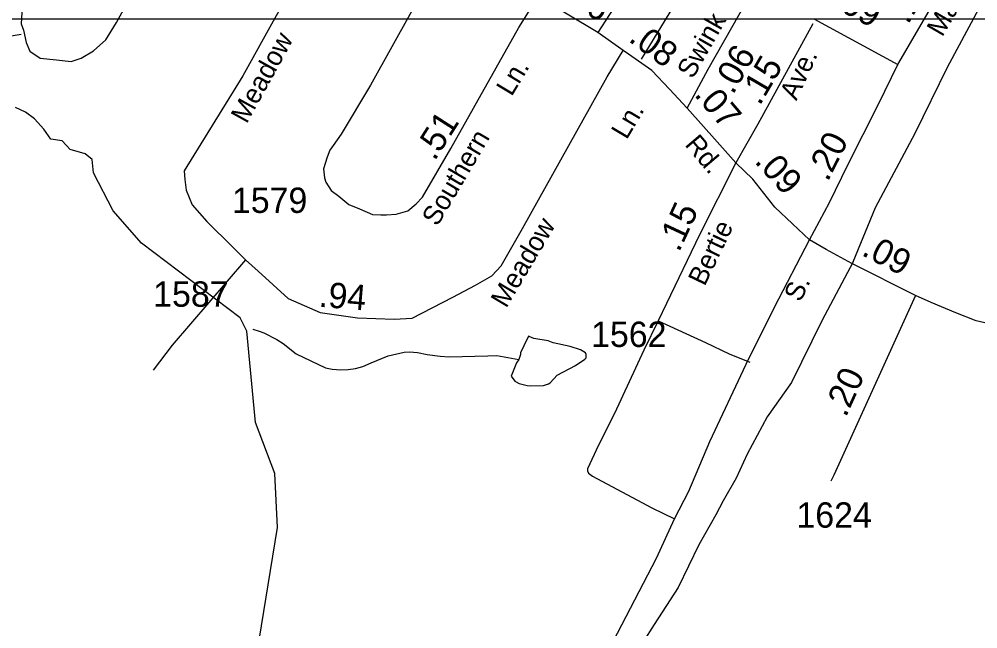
# Model space of a CAD drawing. Extents: x 1473865 to 1648260, y 639067 to 773536.
# Drawn here: x 1537453 to 1542181, y 675669 to 678674 of the extents above; entities that cross this region are included whole.
import ezdxf

# ---------------------------------------------------------------- set-up
doc = ezdxf.new("R2010")
doc.units = 0
for name, color, linetype in [('Exist Hydrographic Creek Single Shore', 7, 'Continuous'), ('Exist Hydrographic Misc Water Feature', 7, 'Continuous'), ('Exist Railroad Mainline', 7, 'Continuous'), ('Exist Road Non-System Type 51', 7, 'Continuous'), ('Exist Road Primary US Label', 7, 'Continuous'), ('Exist Road Primary US Mileage Hundredths English Label', 7, 'Continuous'), ('Exist Road Primary US UnDivided 4 Lane Attributed', 7, 'Continuous'), ('Exist Road Secondary Mileage Hundredths English Label', 7, 'Continuous'), ('Exist Road Secondary Type 51 Attributed', 7, 'Continuous'), ('Exist Road Secondary Type 51 Label', 7, 'Continuous'), ('Exist Road Secondary Type 51 Number Label', 7, 'Continuous'), ('Map Preparation Inset Cut Line', 7, 'Continuous')]:
    doc.layers.add(name, color=color, linetype=linetype)

msp = doc.modelspace()

# ---------------------------------------------------------------- linework, layer by layer
at = {"layer": 'Exist Hydrographic Creek Single Shore'}
msp.add_lwpolyline([(1538639.3, 674876.1), (1538615.3, 674942.2), (1538625.3, 675542.7), (1538726.3, 676167.6), (1538714.3, 676433.7), (1538618.3, 676685.2), (1538575.3, 677135.8), (1538542.3, 677202), (1538056.3, 677569.6), (1537917.3, 677730), (1537820.3, 677915.8), (1537813.3, 677981.5), (1537779.2, 678009.6), (1537704.7, 678031.6), (1537664.7, 678074.4), (1537609.6, 678082.6), (1537575.1, 678132.3), (1537528.2, 678183.3), (1537484.1, 678215), (1537434.5, 678238.4)], dxfattribs=at)
at = {"layer": 'Exist Hydrographic Misc Water Feature'}
for points in [[(1538604.6, 677146.6), (1538636.4, 677136.1), (1538660.3, 677127.4), (1538723.8, 677094.9), (1538755.6, 677074.6), (1538818.8, 677024.9), (1538963.7, 676954.7), (1538995.8, 676948.3), (1539039.6, 676945.8), (1539075.7, 676947.5), (1539111.7, 676952.5), (1539147.8, 676961.7), (1539188.2, 676979.7), (1539272.8, 677014.1), (1539351.1, 677033), (1539377.3, 677034.2), (1539417.1, 677030.1), (1539464.9, 677020.9), (1539528.8, 677012.2), (1539572.9, 677009.7), (1539764.9, 677014), (1539809.1, 677015.6), (1539916.8, 676996.2)], [(1539916.8, 676996.2), (1539906.4, 676980), (1539879.4, 676914.9), (1539897.1, 676889.9), (1539918.9, 676878), (1539958.8, 676869), (1539974.7, 676867), (1540038.8, 676868.2), (1540062.9, 676875.9), (1540071, 676881.5), (1540105.6, 676918.5), (1540196.4, 676967.6), (1540242.9, 676998.6), (1540249.1, 677005.1), (1540249.2, 677020.7), (1540245.5, 677028.9), (1540221.6, 677043.4), (1540169.8, 677060), (1540086.1, 677079), (1540062.2, 677087.6), (1539990.6, 677100.5), (1539968.5, 677109.2), (1539964.6, 677110.9), (1539941.8, 677063.8), (1539925.3, 677029.6), (1539925.2, 677021.4), (1539916.8, 676996.2)]]:
    msp.add_lwpolyline(points, dxfattribs=at)
at = {"layer": 'Exist Railroad Mainline'}
for points in [[(1541566.6, 677477.4), (1541676.7, 677746.3), (1541871, 678112.8), (1542030.9, 678437.7), (1542185.9, 678724.9), (1542339.4, 679030.2), (1542486.3, 679311.6), (1542600.1, 679533.6), (1542691.3, 679713.8)], [(1541566.6, 677477.4), (1541410.8, 677186.4), (1541261.9, 676883.1), (1541142.4, 676714), (1541043.3, 676529.7)], [(1541043.3, 676529.7), (1540989, 676410.7), (1540925.2, 676299.9)], [(1540925.2, 676299.9), (1540888, 676230.5), (1540805.3, 676082.1), (1540703.6, 675871.8), (1540584.5, 675690.1), (1540475.4, 675520), (1540139.4, 675062.2), (1539749.9, 674519.2), (1539411.7, 674053.4), (1538995.4, 673472.9), (1538635.2, 672997.3), (1538321.7, 672573), (1538077.8, 672237.6), (1537807.3, 671872.4), (1537581.9, 671562.4), (1537297.1, 671169.6)]]:
    msp.add_lwpolyline(points, dxfattribs=at)
at = {"layer": 'Exist Road Non-System Type 51'}
msp.add_line((1540645.3, 677272.7), (1540604.1, 677187.1), dxfattribs=at)
for points in [[(1540725.2, 679268.2), (1540604, 679090.6), (1540422.4, 678788.1), (1540307.5, 678609.1)], [(1540980.7, 679239.5), (1540757.7, 678865.8), (1540521.1, 678477.2)], [(1537218.1, 678547.7), (1537344.4, 678579.6), (1537463.3, 678600.6)], [(1538569.2, 677488.4), (1538208.1, 677066.7), (1538113.8, 676944.6)], [(1540604.1, 677187.1), (1540533.4, 677042.4), (1540388.4, 676730.2), (1540310.6, 676574.9), (1540256.4, 676457.9), (1540255, 676446.9), (1540260, 676435.8), (1540279.7, 676421.4), (1540572.9, 676265.8), (1540684.7, 676210.8)], [(1540604.1, 677187.1), (1540838.1, 677080.7), (1540955, 677024.5), (1541057, 676983.4)]]:
    msp.add_lwpolyline(points, dxfattribs=at)
at = {"layer": 'Exist Road Primary US UnDivided 4 Lane Attributed'}
for points in [[(1541786.4, 678451.2), (1542055.1, 678914.1), (1542123.7, 679050.4)], [(1541350.1, 677586.3), (1541449.7, 677769.9), (1541539.3, 677956), (1541690.8, 678255.1), (1541786.4, 678451.2)], [(1538792, 673607.6), (1539310.8, 674301.1), (1539490.8, 674513.8), (1539642.4, 674704.8), (1539990, 675114.2), (1540169.8, 675316.7), (1540339.6, 675523.4), (1540596.9, 676016.4), (1540684.7, 676210.8), (1540755.1, 676347.4), (1540859.1, 676591.4), (1541038.4, 676973.9), (1541178.3, 677254.4), (1541350.1, 677586.3)]]:
    msp.add_lwpolyline(points, dxfattribs=at)
at = {"layer": 'Exist Road Secondary Type 51 Attributed'}
msp.add_line((1541372.2, 678676.1), (1541786.4, 678451.2), dxfattribs=at)
for points in [[(1539111, 679363.5), (1538942.9, 679082.6), (1538713.9, 678678.2), (1538555.4, 678394.2), (1538266.5, 677925.8), (1538270, 677883.6), (1538276.4, 677831), (1538306.6, 677759.4), (1538378.3, 677676.1), (1538507.4, 677549.8), (1538569.2, 677488.4), (1538632.1, 677431.1), (1538779.8, 677297.3), (1538937.5, 677228.4), (1539121, 677202.6), (1539302.5, 677195.9), (1539390.6, 677199.7), (1539591.3, 677303), (1539703.2, 677363.3), (1539783.5, 677409.2), (1539829.4, 677458), (1539935.5, 677641.7), (1540353.5, 678389.6), (1540430.9, 678518.8)], [(1539585.1, 679057.9), (1539387.3, 678711.3), (1539185.5, 678348.7), (1539041.4, 678106.9), (1539002.1, 678051.4), (1538985.8, 678028.2), (1538971.4, 677993.7), (1538953.1, 677936.2), (1538958.8, 677891.9), (1538965.7, 677870.3), (1538991.5, 677830.1), (1539030, 677800.9), (1539078.4, 677760.8)], [(1540747.6, 678235.7), (1540851.5, 678428.1), (1541085.1, 678839.6)], [(1539078.4, 677760.8), (1539130.8, 677739), (1539195, 677711), (1539236.2, 677708.8), (1539263.9, 677709.6), (1539312.7, 677712.5), (1539370, 677729.7), (1539411.1, 677763.4), (1539441.4, 677797.4), (1539582.3, 678036.8), (1539917.6, 678633.6), (1540012.2, 678785.7)], [(1540430.9, 678518.8), (1540307.5, 678609.1), (1540012.2, 678785.7)], [(1537468.7, 678763.2), (1537463.4, 678650.7), (1537474.5, 678620.3), (1537486.9, 678559.7), (1537504.8, 678515.6), (1537557.2, 678481.1), (1537637.1, 678472.8), (1537708.8, 678465.9), (1537758.5, 678481.1), (1537819.1, 678518.3), (1537880.4, 678572.9), (1537932.2, 678657.1), (1537994.8, 678772.7)], [(1541366.4, 678651.6), (1541096.1, 678156), (1540987.5, 677965.4)], [(1540747.6, 678235.7), (1540659.4, 678329.4), (1540572.5, 678420.4), (1540458.6, 678501.8), (1540430.9, 678518.8)], [(1540987.5, 677965.4), (1540895.1, 678068.8), (1540747.6, 678235.7)], [(1540987.5, 677965.4), (1540808.2, 677611.2), (1540645.3, 677272.7)], [(1541350.1, 677586.3), (1541267, 677664.6), (1541179.3, 677747.8), (1541071.8, 677885), (1540987.5, 677965.4)], [(1541872.7, 677311.9), (1541559.7, 677469.1), (1541432.8, 677538), (1541350.1, 677586.3)], [(1541872.7, 677311.9), (1541470.1, 676426.8), (1541456.3, 676396.4)], [(1544015.3, 676897.9), (1543706.2, 676958.2), (1543167.3, 677012.7), (1542713.7, 677074.8), (1542528.9, 677107.9), (1542377.3, 677138.2), (1542251.8, 677168.5), (1542173.2, 677187.8), (1542072.6, 677226.4), (1541951.2, 677277.4), (1541872.7, 677311.9)]]:
    msp.add_lwpolyline(points, dxfattribs=at)
at = {"layer": 'Map Preparation Inset Cut Line'}
for points in [[(1530807.2, 678673.7), (1530807.2, 722115.9), (1605695.7, 722115.9), (1605695.7, 695030), (1593323.3, 695030), (1593323.3, 678673.7), (1530807.2, 678673.7)], [(1481537.9, 640573), (1544130.8, 640573), (1544130.8, 678673.7), (1481537.9, 678673.7), (1481537.9, 640573)]]:
    msp.add_lwpolyline(points, dxfattribs=at)

# ---------------------------------------------------------------- texts
at = {"layer": 'Exist Road Primary US Label'}
for s, rotation, p in [('Main', 59.8637, (1542005.5, 678582.6)), ('S.', 64.554, (1541306.1, 677275.2))]:
    msp.add_text(s, height=95, rotation=rotation, dxfattribs=at).set_placement(p)
at = {"layer": 'Exist Road Primary US Mileage Hundredths English Label'}
for s, rotation, p in [('.13', 59.8637, (1541836.6, 678644.2)), ('.20', 63.1343, (1541440.5, 677869))]:
    msp.add_text(s, height=125, rotation=rotation, dxfattribs=at).set_placement(p)
at = {"layer": 'Exist Road Secondary Mileage Hundredths English Label'}
for s, rotation, p in [('.16', 326.3054, (1540122.7, 678785.2)), ('.09', 331.5064, (1541456.4, 678739.1)), ('.08', 323.3398, (1540453.1, 678568.7)), ('.06', 60.4146, (1540973.4, 678297.9)), ('.15', 59.6985, (1541105.3, 678243.7)), ('.07', 310.3567, (1540778.5, 678300.3)), ('.51', 57.5099, (1539501.8, 677971.3)), ('.09', 312.5606, (1541075.4, 677969.8)), ('.15', 65.0374, (1540707.2, 677521.4)), ('.09', 332.6036, (1541602.3, 677513.2)), ('.94', 355.3149, (1538927.9, 677256.7)), ('.20', 65.6904, (1541529.8, 676707.4))]:
    msp.add_text(s, height=125, rotation=rotation, dxfattribs=at).set_placement(p)
at = {"layer": 'Exist Road Secondary Type 51 Label'}
for s, rotation, p in [('Swink', 60.4146, (1540774.7, 678375.2)), ('Meadow', 61.0452, (1538574.9, 678154.8)), ('Ave.', 65.0374, (1541285.9, 678268.8)), ('Ln.', 58.9313, (1539881.4, 678289.6)), ('Ln.', 59.201, (1540448.7, 678076.4)), ('Southern', 59.452, (1539515.1, 677648.5)), ('Rd.', 310.3567, (1540732.1, 678054.1)), ('Meadow', 59.201, (1539854.7, 677245.8)), ('Bertie', 64.3049, (1540833.5, 677353.8))]:
    msp.add_text(s, height=95, rotation=rotation, dxfattribs=at).set_placement(p)
at = {"layer": 'Exist Road Secondary Type 51 Number Label'}
for s, p in [('1579', (1538502.2, 677718.9)), ('1587', (1538113.9, 677256.4)), ('1562', (1540273.4, 677058.2)), ('1624', (1541286.2, 676167.4))]:
    msp.add_text(s, height=125, dxfattribs=at).set_placement(p)

doc.saveas('drawing.dxf')
